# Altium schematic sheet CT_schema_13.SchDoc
size 382 x 278 mm
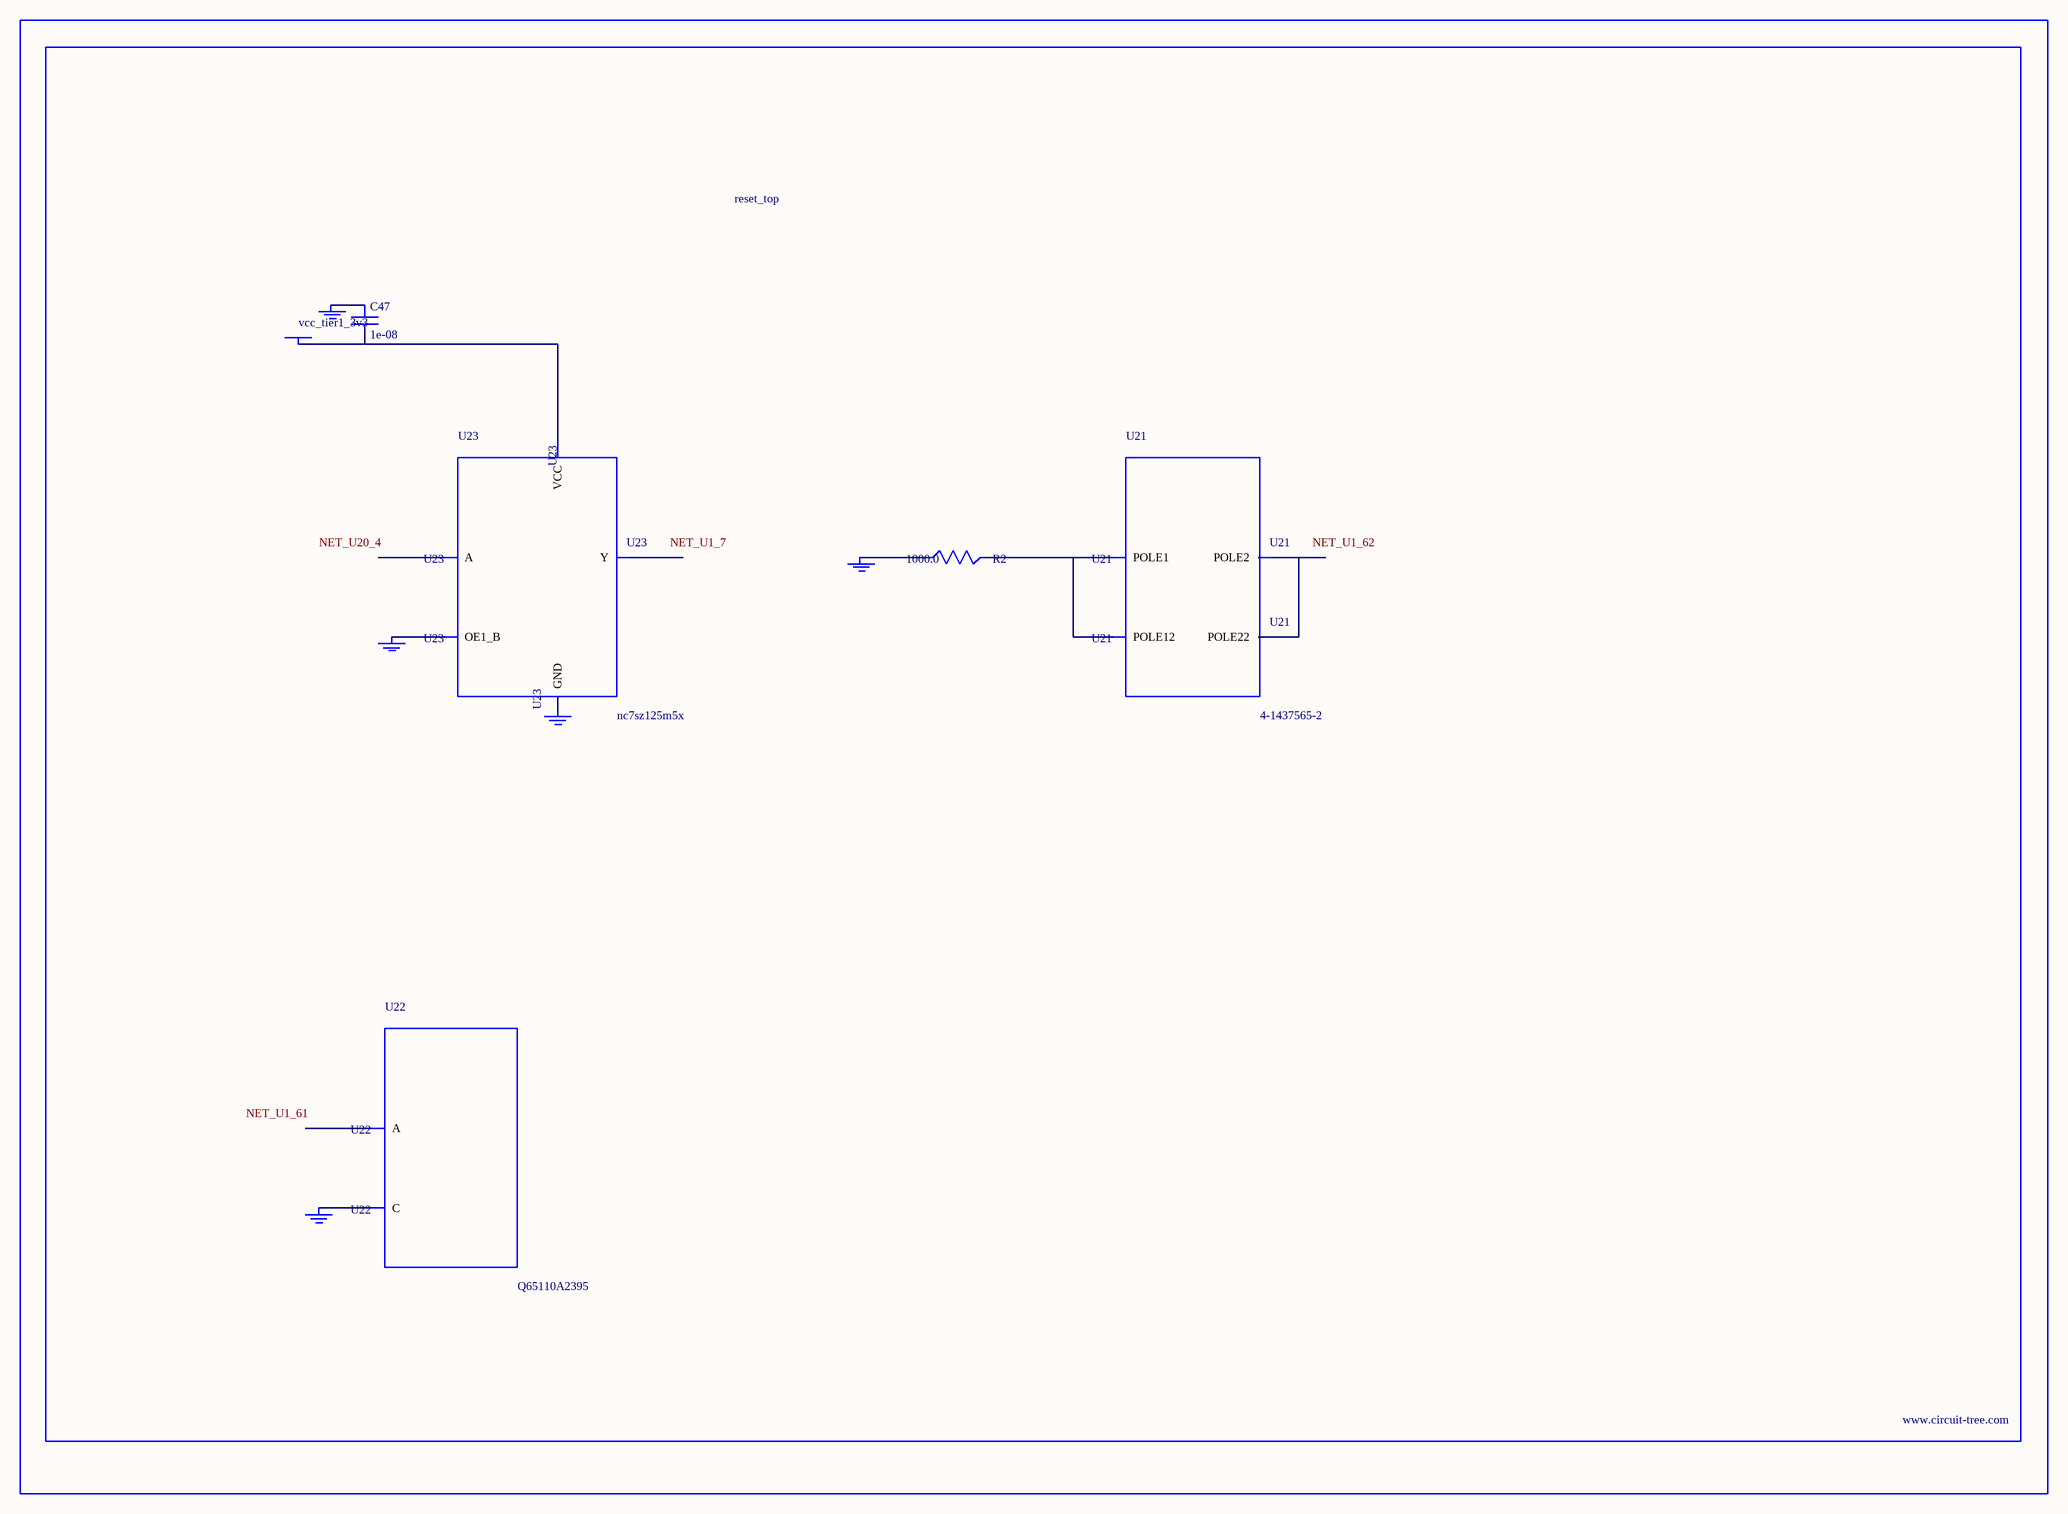
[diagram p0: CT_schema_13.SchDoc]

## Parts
BORDER12  (no value)
C47  1e-08  [C0402]
GND_INSTANCE_12_0  (no value)
GND_INSTANCE_12_1  (no value)
GND_INSTANCE_12_2  (no value)
GND_INSTANCE_12_3  (no value)
GND_INSTANCE_12_4  (no value)
POWER_INSTANCE_12_0  vcc_tier1_3v3
R2  1000.0  [R0603]
U21  4-1437565-2  [SW_4-1437565-2]
U22  Q65110A2395  [LGM67K-G1J2-24-Z]
U23  nc7sz125m5x  [NC7SZ125M5X]

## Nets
NetC47_1: C47.1 GND_INSTANCE_12_2.0(GND)
NetC47_2: C47.2 POWER_INSTANCE_12_0.0(PWR) U23.5(VCC)
NetGND_INSTANCE_12_0_0: GND_INSTANCE_12_0.0(GND) R2.1
NetGND_INSTANCE_12_1_0: GND_INSTANCE_12_1.0(GND) U22.C
NetGND_INSTANCE_12_3_0: GND_INSTANCE_12_3.0(GND) U23.1(OE1_B)
NetGND_INSTANCE_12_4_0: GND_INSTANCE_12_4.0(GND) U23.3(GND)
NetR2_2: R2.2 U21.1(POLE1) U21.2(POLE12)
NetU21_3: U21.3(POLE2) U21.4(POLE22)

Not connected (* = marked no-connect by the designer): U22 A; U23 2(A) 4(Y)

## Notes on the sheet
- Labels drawn without touching a wire or pin: NET_U1_7, NET_U1_61, NET_U1_62, NET_U20_4

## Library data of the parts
BORDER12 = BORDER_PAGE12
C47 = C0402C103K3RAC
GND_INSTANCE_12_0-GND_INSTANCE_12_4 = GND
POWER_INSTANCE_12_0 = PWR
R2 = RC0603JR-071KL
